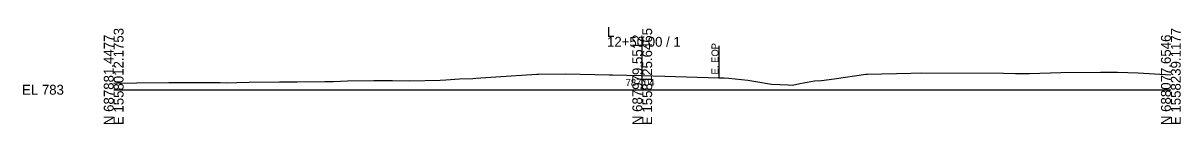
# Model space of a CAD drawing. Extents: x -26 to 2603, y -3010 to 9589.
# Drawn here: x 1274.3 to 1602.8, y -2509.7 to -2482.2 of the extents above; entities that cross this region are included whole.
import ezdxf

# ---------------------------------------------------------------- set-up
doc = ezdxf.new("R2010")
doc.units = 0
for name, color, linetype in [('Exist Cross Section Cell', 7, 'Continuous'), ('Exist XS Center Line Elevation Label', 7, 'Continuous'), ('Exist XS Ground Line', 7, 'Continuous'), ('Prop XS Label Text', 7, 'Continuous')]:
    doc.layers.add(name, color=color, linetype=linetype)

msp = doc.modelspace()

# ---------------------------------------------------------------- linework, layer by layer
at = {"layer": 'Exist Cross Section Cell'}
for p, q in [((1450, -2500), (1450, -2485.03)), ((1300, -2500), (1450, -2500)), ((1450, -2500), (1600, -2500))]:
    msp.add_line(p, q, dxfattribs=at)
at = {"layer": 'Exist XS Ground Line'}
msp.add_lwpolyline([(1300, -2498.1), (1306.44, -2498.02), (1315.67, -2497.97), (1317.54, -2497.98), (1328.71, -2497.91), (1330.19, -2497.93), (1332.09, -2498.05), (1334.93, -2497.99), (1338.46, -2497.88), (1347.02, -2497.78), (1352.05, -2497.73), (1359.95, -2497.66), (1362.41, -2497.63), (1366.33, -2497.5), (1373.82, -2497.34), (1379.1, -2497.37), (1384.02, -2497.48), (1392.69, -2497.26), (1394.23, -2497.15), (1398.17, -2496.93), (1401.95, -2496.8), (1402.76, -2496.75), (1408.4, -2496.37), (1420.08, -2495.6), (1420.52, -2495.6), (1428.17, -2495.5), (1440.66, -2495.77), (1441.55, -2495.79), (1449.71, -2495.95), (1456.41, -2496.18), (1471.74, -2496.6), (1473.27, -2496.63), (1474.58, -2496.74), (1479.95, -2497.28), (1482.25, -2497.67), (1486.63, -2498.37), (1491.43, -2498.61), (1492.68, -2498.66), (1494.73, -2498.21), (1498.89, -2497.48), (1500.84, -2497.42), (1504.47, -2496.95), (1513.45, -2495.63), (1513.88, -2495.59), (1526.2, -2495.28), (1529.32, -2495.24), (1552.55, -2495.33), (1555.91, -2495.41), (1559.93, -2495.37), (1568.77, -2495.15), (1580.06, -2495.01), (1584.83, -2495.01), (1590.71, -2495.25), (1600, -2495.74)], dxfattribs=at)
at = {"layer": 'Prop XS Label Text'}
msp.add_line((1471.74, -2487.6), (1471.74, -2496.6), dxfattribs=at)

# ---------------------------------------------------------------- texts
at = {"layer": 'Exist Cross Section Cell'}
for s, p in [('E 1558012.1753', (1302.8, -2510)), ('E 1558125.6465', (1452.8, -2510)), ('E 1558239.1177', (1602.8, -2510)), ('N 687881.4477', (1300, -2510)), ('N 687979.5512', (1450, -2510)), ('N 688077.6546', (1600, -2510))]:
    msp.add_text(s, height=2.8, rotation=90, dxfattribs=at).set_placement(p)
for s, p in [('L', (1440, -2485.03)), ('12+50.00 / 1', (1440, -2487.83)), ('EL 783', (1274, -2501.4))]:
    msp.add_text(s, height=2.8, dxfattribs=at).set_placement(p)
at = {"layer": 'Exist XS Center Line Elevation Label'}
msp.add_text('787.04', height=2, dxfattribs=at).set_placement((1445.28, -2498.96))
at = {"layer": 'Prop XS Label Text'}
msp.add_text('E. EOP', height=2, rotation=90, dxfattribs=at).set_placement((1471.64, -2495.68))

doc.saveas('drawing.dxf')
